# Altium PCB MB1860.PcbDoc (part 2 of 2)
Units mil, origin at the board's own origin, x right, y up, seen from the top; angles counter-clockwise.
Board outline 5005.03 x 3784.67 mil, 2 copper layers (Top Layer, Bottom Layer), stack 61.811 mil thick; 42 components, 46 nets, 183 pads, 524 vias.
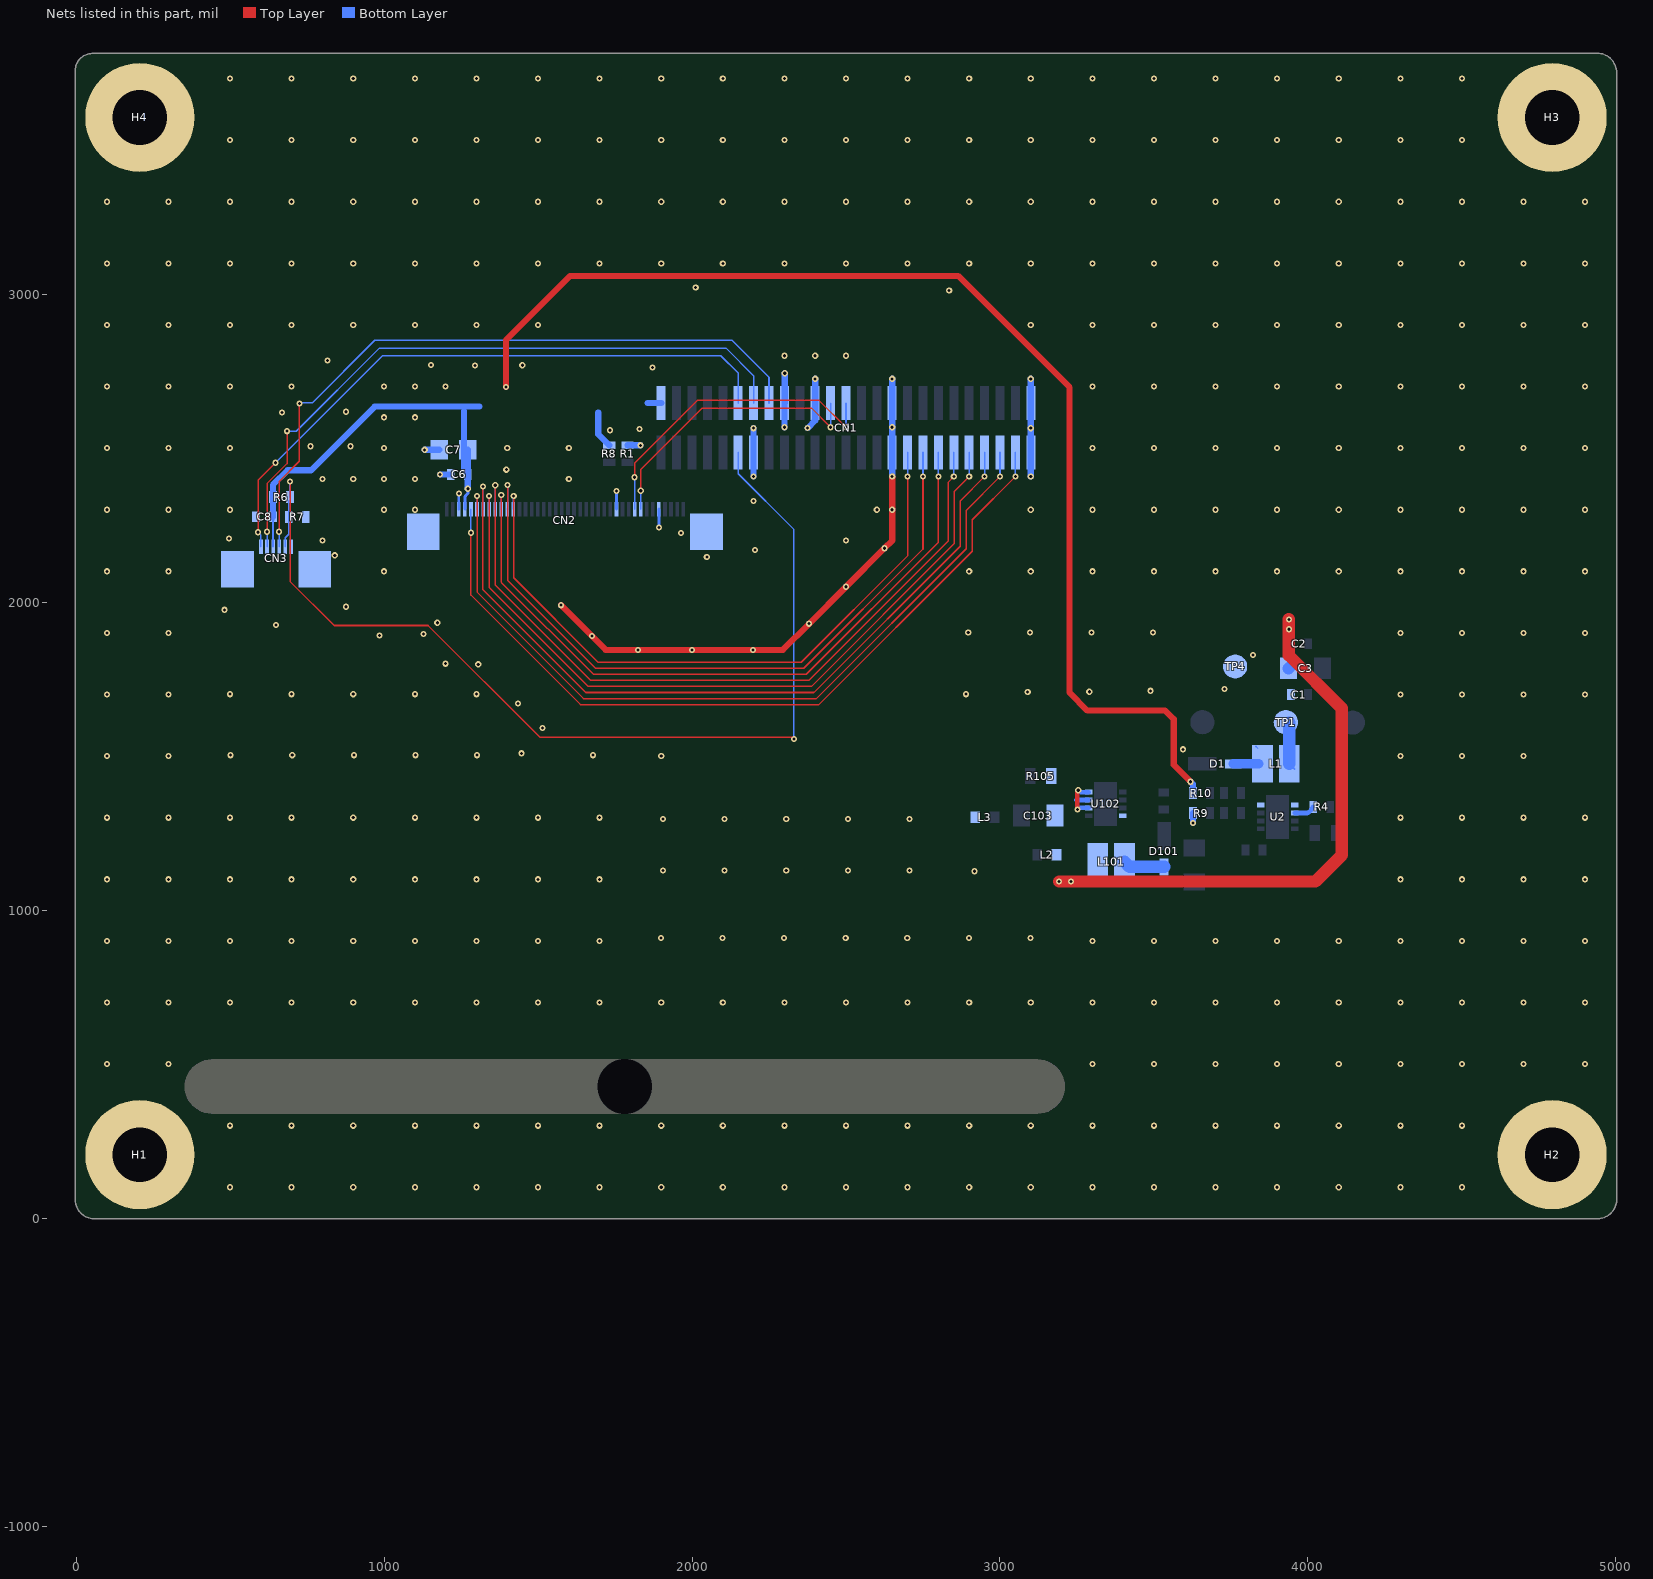
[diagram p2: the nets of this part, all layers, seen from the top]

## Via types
v1: diameter 20, hole 10, Top Layer to Bottom Layer, tented both sides, 524 vias

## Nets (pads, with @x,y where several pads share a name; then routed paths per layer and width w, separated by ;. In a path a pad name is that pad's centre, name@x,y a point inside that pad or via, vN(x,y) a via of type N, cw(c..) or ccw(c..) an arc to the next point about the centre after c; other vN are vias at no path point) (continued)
GND: C6.1 C7.2 C8.1 CN1.1 CN1.2 CN1.19 CN1.20 CN1.30 CN1.34 CN1.37 CN2.5 CN2.12 CN2.38 CN2.MP1 CN2.MP2 CN3.1 CN3.MP1 CN3.MP2 H1.1 H2.1 H3.1 H4.1 L3.1 R1.1 R7.1 R9.2 TP4.1 | length 2955.2
  Top Layer w20: v1(1575,1990) v1(1675,1890) 1720,1845 v1(1825,1845) v1(2000,1845) v1(2198,1845) 2295,1845 v1(2380,1930) v1(2500,2050) v1(2625,2175) 2650,2200 v1(2650,2300) v1(2650,2407.44)
  Bottom Layer w8: CN2.38@1242.91,2301.69 v1@1242.91,2352.46
  Bottom Layer w10: v1@1242.91,2352.46 v1(1243,2352.54) ; CN2.12@1754.73,2301.69 v1(1754.72,2360.82) ; CN2.5@1892.52,2301.69 1893,2301.21 v1(1893,2242)
  Bottom Layer w20: v1(1132,2494.54) C7.2@1179.48,2494.54 ; v1(1182,2414.54) C6.1@1216.88,2414.54 ; R1.1@1790.72,2509.1 v1(1833,2509.1) ; v1(2200,2407.44) CN1.37@2200,2486.1 v1(2200,2564.76) ; v1(2300,2567.68) CN1.34@2300,2646.34 2301,2647.34 v1(2301,2743) ; v1(2375,2565) 2400,2590 CN1.30@2400,2646.34 v1(2400,2725) ; v1(2650,2407.44) CN1.19@2650,2486.1 v1(2650,2567.68) CN1.20@2650,2646.34 v1(2650,2725) ; v1(3100,2407.44) CN1.1@3100,2486.1 v1(3100,2564.76) CN1.2@3100,2646.34 v1(3100,2725) ; v1(3626.44,1282.44) R9.2@3626.44,1315
  other v1: 500,100 700,100 900,100 1100,100 1300,100 1500,100 1700,100 1900,100 2100,100 2300,100 2500,100 2700,100 2900,100 3100,100 3300,100 3500,100 3700,100 3900,100 4100,100 4300,100 4500,100 500,300 700,300 900,300 1100,300 1300,300 1500,300 1700,300 1900,300 2100,300 2300,300 2500,300 2700,300 2900,300 3100,300 3300,300 3500,300 3700,300 3900,300 4100,300 4300,300 4500,300 100,500 300,500 3300,500 3500,500 3700,500 3900,500 4100,500 4300,500 4500,500 4700,500 4900,500 100,700 300,700 500,700 700,700 900,700 1100,700 1300,700 1500,700 1700,700 1900,700 2100,700 2300,700 2500,700 2700,700 2900,700 3100,700 3300,700 3500,700 3700,700 3900,700 4100,700 4300,700 4500,700 4700,700 4900,700 100,900 300,900 500,900 700,900 900,900 1100,900 1300,900 1500,900 1700,900 3300,900 3500,900 3700,900 3900,900 4100,900 4300,900 4500,900 4700,900 4900,900 1899,909 2099,909 2299,909 2499,909 2699,909 2899,909 3099,909 100,1100 300,1100 500,1100 700,1100 900,1100 1100,1100 1300,1100 1500,1100 1700,1100 4300,1100 4500,1100 4700,1100 4900,1100 2917,1126 1906,1128 2106,1128 2306,1128 2506,1128 2706,1128 1906,1296 2106,1296 2306,1296 2506,1296 2706,1296 100,1300 300,1300 500,1300 700,1300 900,1300 1100,1300 1300,1300 1500,1300 1700,1300 4300,1300 4500,1300 4700,1300 4900,1300 100,1500 300,1500 1900,1500 4300,1500 4500,1500 4700,1500 502,1503 702,1503 902,1503 1102,1503 1302,1503 1679,1503 1446,1509 3594,1522 1515,1591 1435,1671 100,1700 300,1700 4300,1700 4500,1700 4700,1700 4900,1700 500,1701 700,1701 900,1701 1100,1701 1300,1701 2890,1701 3090,1708 3290,1709 3489,1712 3729,1718 1306,1798 1200,1800 3822,1828 985,1892 1128,1897 100,1900 300,1900 4300,1900 4500,1900 4700,1900 4900,1900 2897,1901 3097,1901 3297,1901 3497,1901 649.61,1925.32 1173,1933 482,1975 876,1985 100,2100 300,2100 1000,2100 2900,2100 3100,2100 3300,2100 3500,2100 3700,2100 3900,2100 4100,2100 4300,2100 4500,2100 4700,2100 4900,2100 2048,2146 840,2152 2205,2169 800,2200 2500,2200 497,2207 1964.37,2224 100,2300 300,2300 500,2300 1000,2300 1100,2300 2600,2300 3100,2300 3300,2300 3500,2300 3700,2300 3900,2300 4100,2300 4300,2300 4500,2300 4700,2300 4900,2300 2200,2328 800,2400 900,2400 1000,2400 1100,2400 1600,2400 1397,2430 100,2500 300,2500 500,2500 1000,2500 1400,2500 1600,2500 3300,2500 3500,2500 3700,2500 3900,2500 4100,2500 4300,2500 4500,2500 4700,2500 4900,2500 761,2506 891,2506 1734,2558 1830,2562 1000,2600 1100,2600 669,2616 877,2618 100,2700 300,2700 500,2700 700,2700 1000,2700 1100,2700 1200,2700 3300,2700 3500,2700 3700,2700 3900,2700 4100,2700 4300,2700 4500,2700 4700,2700 4900,2700 1872,2762 1295,2768 1449,2769 1153,2770 816,2785 2300,2800 2400,2800 2500,2800 100,2900 300,2900 500,2900 700,2900 900,2900 1100,2900 1300,2900 1500,2900 3100,2900 3300,2900 3500,2900 3700,2900 3900,2900 4100,2900 4300,2900 4500,2900 4700,2900 4900,2900 2835,3012 2012,3021 100,3100 300,3100 500,3100 700,3100 900,3100 1100,3100 1300,3100 1500,3100 1700,3100 1900,3100 2100,3100 2300,3100 2500,3100 2700,3100 2900,3100 3100,3100 3300,3100 3500,3100 3700,3100 3900,3100 4100,3100 4300,3100 4500,3100 4700,3100 4900,3100 100,3300 300,3300 500,3300 700,3300 900,3300 1100,3300 1300,3300 1500,3300 1700,3300 1900,3300 2100,3300 2300,3300 2500,3300 2700,3300 2900,3300 3100,3300 3300,3300 3500,3300 3700,3300 3900,3300 4100,3300 4300,3300 4500,3300 4700,3300 4900,3300 500,3500 700,3500 900,3500 1100,3500 1300,3500 1500,3500 1700,3500 1900,3500 2100,3500 2300,3500 2500,3500 2700,3500 2900,3500 3100,3500 3300,3500 3500,3500 3700,3500 3900,3500 4100,3500 4300,3500 4500,3500 500,3700 700,3700 900,3700 1100,3700 1300,3700 1500,3700 1700,3700 1900,3700 2100,3700 2300,3700 2500,3700 2700,3700 2900,3700 3100,3700 3300,3700 3500,3700 3700,3700 3900,3700 4100,3700 4300,3700 4500,3700
HSYNC: CN1.26 CN2.9 | length 1032
  Top Layer w5: v1@1813.78,2408.78 1813.78,2451.78 2017,2655 2412.68,2655 v1(2500,2567.68)
  Bottom Layer w5: CN2.9@1813.78,2301.69 1813.78,2385.54 v1(1813.78,2405.51) ; v1(2500,2567.68) CN1.26@2500,2646.34
I2C_SCL: CN1.40 CN3.6 | length 2067.2
  Top Layer w5: v1(591,2226.86) 591,2396 v1(647.5,2452.5)
  Bottom Layer w5: v1(591,2226.86) 600.39,2217.46 CN3.6@600.39,2179.66 ; v1(647.5,2452.5) 995,2800 2093.58,2800 2150,2743.58 CN1.40@2150,2646.34
I2C_SDA: CN1.38 CN3.5 | length 2155
  Top Layer w5: v1(620.08,2228.41) 620.08,2385.08 685,2450 v1(685,2555)
  Bottom Layer w5: CN3.5@620.08,2179.66 v1(620.08,2228.41) ; v1(685,2555) 715,2555 985,2825 2110,2825 2200,2735 CN1.38@2200,2646.34
INT: CN1.39 CN3.2 R6.1 R7.2 | length 3383.7
  Top Layer w5: v1(695,2391.86) 695,2067 838,1924 1143,1924 1506,1561 2326,1561 v1(2331,1556)
  Bottom Layer w5: CN3.2@679.13,2179.66 679.13,2208.99 690.44,2220.3 R7.2@690.44,2276.86 R6.1@690.44,2329.86 ; R6.1@694.56,2340.86 694.56,2391.42 v1(695,2391.86) ; CN1.39@2150,2486.1 2150,2417 2331,2236 v1(2331,1556)
NetD1_1: D1.1 L1.2 U2.8 | length 91.5
  Bottom Layer w5: L1.2@3830.57,1532 L1.2@3836.48,1526.09
  Bottom Layer w30: D1.1@3757.39,1475 L1.2@3840.57,1475
NetD101_1: D101.1 L101.2 U102.8 | length 135.6
  Bottom Layer w40: L101.2@3404.31,1157 3421.08,1140.23 D101.1@3533,1140.23
NetR4_2: R4.2 U2.2 | length 70.3
  Bottom Layer w15: U2.2@3956.72,1315.16 3997.54,1315.16 3998.89,1316.5 4001.25,1316.5 4011.5,1326.75 4011.5,1329.11 R4.2@4017.39,1335
NetR105_2: R105.2 U102.2 U102.4 | length 138.5
  Top Layer w15: v1(3251.24,1327) 3251.24,1386 v1(3254.24,1389)
  Bottom Layer w15: v1(3251.24,1327) 3256,1331.76 U102.2@3288.12,1331.76 ; v1(3254.24,1389) 3260.29,1382.94 U102.4@3288.12,1382.94
R0: CN1.3 CN2.36 | length 2639.1
  Top Layer w5: v1(1282.28,2225.31) 1282.28,2071.77 1282.28,2022.84 1637.92,1667.2 2412.08,1667.2 2910,2165.13 2910,2267.44 v1(3050,2407.44)
  Bottom Layer w5: v1(1282.28,2225.31) CN2.36@1282.28,2301.69 ; v1(3050,2407.44) CN1.3@3050,2486.1
R1: CN1.5 CN2.35 | length 2646.8
  Top Layer w5: v1(1301.97,2344.88) 1301.97,2032.53 1647.61,1686.89 2403.92,1686.89 2890.32,2173.28 2890.32,2297.76 v1(3000,2407.44)
  Bottom Layer w5: CN2.35@1301.97,2301.69 v1(1301.97,2344.88) ; v1(3000,2407.44) CN1.5@3000,2486.1
R2: CN1.7 CN2.34 | length 2631.6
  Top Layer w5: v1(1321,2375.54) 1321,2040.5 1654.92,1706.57 2395.77,1706.57 2870.63,2181.44 2870.63,2328.07 v1(2950,2407.44)
  Bottom Layer w5: v1(1321,2375.54) 1321,2303.04 1322,2302.04 CN2.34@1321.65,2301.69 ; v1(2950,2407.44) CN1.7@2950,2486.1
R3: CN1.9 CN2.33 | length 2491.9
  Top Layer w5: v1(1341,2344.88) 1341,2048.5 1663.24,1726.26 2387.62,1726.26 2850.94,2189.59 2850.94,2358.39 v1(2900,2407.44)
  Bottom Layer w5: v1(1341,2344.88) 1341.34,2344.54 CN2.33@1341.34,2301.69 ; v1(2900,2407.44) CN1.9@2900,2486.1
R4: CN1.11 CN2.32 | length 2483.7
  Top Layer w5: v1(1361,2379.54) 1361,2055.48 1670.54,1745.94 2379.46,1745.94 2831.26,2197.74 2831.26,2388.7 v1(2850,2407.44)
  Bottom Layer w5: CN2.32@1361,2301.72 v1(1361,2379.54) ; v1(2850,2407.44) CN1.11@2850,2486.1
R5: CN1.13 CN2.31 | length 2339.2
  Top Layer w5: 1380.71,2064.19 v1(1380.71,2347.72) ; 1382.46,2062.45 1680.04,1765.63 2371.31,1765.63 2800,2194.32 v1(2800,2407.44)
  Bottom Layer w5: CN2.31@1380.71,2301.69 v1(1380.71,2347.72) ; v1(2800,2407.44) CN1.13@2800,2486.1
R6: CN1.15 CN2.30 | length 2330.1
  Top Layer w5: v1(1401,2380.54) 1401,2071.16 1686.85,1785.32 2363.15,1785.32 2750,2172.16 v1(2750,2407.44)
  Bottom Layer w5: CN2.30@1400.4,2301.69 1401,2302.3 v1(1401,2380.54) ; v1(2750,2407.44) CN1.15@2750,2486.1
R7: CN1.17 CN2.29 | length 2181
  Top Layer w5: v1(1421,2344.88) 1421,2079 1695,1805 2355,1805 2700,2150 v1(2700,2407.44)
  Bottom Layer w5: CN2.29@1420.08,2301.69 1420.08,2343.96 v1(1421,2344.88) ; v1(2700,2407.44) CN1.17@2700,2486.1
VDD: C6.2 C7.1 C8.2 CN1.50 CN2.37 CN3.4 R6.2 R8.1 R10.1 | length 5385.6
  Top Layer w20: v1(1396,2698) 1396,2851 1604,3059 2864,3059 3226,2697 3226,1706 3284,1648 3536,1648 3564,1620 3564,1472 3619,1417 v1(3618.75,1416.75)
  Bottom Layer w6: CN3.4@639.76,2179.66 C8.2@639.76,2267.53
  Bottom Layer w10: C8.2@638,2269.3 C8.2@639.76,2267.53 ; CN2.37@1262.6,2302.15 CN2.37@1262.6,2301.69 CN2.37@1262.65,2301.74 ; CN2.37@1262.91,2302.01 1263,2302.09 1263,2342.84 1264,2343.84 1264,2344.59 1272,2352.59 v1(1272,2368)
  Bottom Layer w20: C8.2@639.56,2276.86 639.44,2276.98 R6.2@639.44,2340.86 639.44,2380.44 687,2428 763,2428 970,2635 1310,2635 ; 1260,2620 1260,2429 C6.2@1272,2417 ; v1(1272,2368) C6.2@1272,2410.61 ; C6.2@1272,2414.54 C6.2@1272,2417 ; C7.1@1272,2494.54 C6.2@1272,2417 ; 1695.43,2615.43 1695.43,2545.1 R8.1@1731.43,2509.1 ; 1856.34,2646.34 CN1.50@1900,2646.34 ; v1(3618.75,1416.75) 3626.44,1409.06 R10.1@3626.44,1380
VL: C1.2 C2.2 C3.2 C103.2 L1.1 L2.2 L101.1 TP1.1 U2.1 U102.3 | length 1991.5
  Top Layer w40: v1(3192,1093) v1(3231,1093) 4024,1093 4110,1179 4110,1655 3937.39,1827.61 3938,1828.23 v1(3938,1912) v1(3938,1944)
  Bottom Layer w5: TP1.1@3937.39,1610 TP1.1@3939,1608.39 ; L1.1@3939,1475 L1.1@3956.72,1457.28
  Bottom Layer w15: 3248.59,1357.35 U102.3@3288.12,1357.35
  Bottom Layer w39.37: C3.2@3937.39,1785 C3.2@3938,1785.61
  Bottom Layer w40: L1.1@3939,1475 TP1.1@3939,1608.39
VSYNC: CN1.28 CN2.8 | length 932.4
  Top Layer w5: v1(1833.47,2361.54) 1833.47,2430.47 2033,2630 2387.68,2630 v1(2450,2567.68)
  Bottom Layer w5: CN2.8@1833.47,2301.69 v1(1833.47,2361.54) ; v1(2450,2567.68) CN1.28@2450,2646.34
WAKE: CN1.36 CN3.3 | length 2242.3
  Top Layer w5: v1(659.45,2228.41) 659.45,2391.45 725,2457 v1(725,2645) v1@725,2650
  Bottom Layer w5: CN3.3@659.45,2179.66 v1(659.45,2228.41) ; v1@722.5,2647.5 767.5,2647.5 970,2850 2130,2850 2250,2730 CN1.36@2250,2646.34
pads on no net: CN1.41 CN1.42 CN1.44 CN1.46 CN1.48 CN2.1 CN2.2 CN2.3 CN2.4 CN2.6 U2.5
copper on no net:
  other v1: 569,2410 633,2506 3154,2574 1044,2773 2998,2829 2891,2949

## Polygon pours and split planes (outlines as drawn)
GND on Bottom Layer "GND-Layer 1-No Net" (solid, remove dead copper, pour order 30): 100,40 40,100 40,3680 100,3740 4920,3740 4960,3700 4960,100 4900,40
BL_A on Bottom Layer "TOP-No Net" (solid, pour order 28): 3586,1171 3682,1171 3701,1190 3701,1254 3693,1262 3613,1262 3602,1273 3602,1328 3583,1347 3482,1347 3466,1331 3466,1204 3480,1190 3565,1190 3583,1172
BLGND on Bottom Layer "TOP-No Net" (solid, pour order 26): 4007,1950 4140,1950 4215,1875 4215,1065 4122,972 3017,972 2971,1018 2971,1496 3074.46,1599.46 3186.54,1599.46 3329,1457 3366,1457 3380,1443 3380,1437 3368.43,1425.43 3305.57,1425.43 3229,1502 3145,1502 3119.44,1476.44 3119.44,1363.83 3095.25,1339.64 3095.25,1240.25 3086,1231 3086,1104 3149,1041 3558,1041 3570,1053 3570,1096 3589,1115 3670,1115 3695,1090 3797,1090 3834,1127 3834,1209 3866,1241 3866,1373 3874,1381 3929.26,1381 3945.89,1364.37 3945.89,1170.11 3957,1159 4044,1159 4061,1176 4059,1178 4059,1368 4016,1411 4016,1636 3990,1662 3990,1933
VL on Bottom Layer "TOP-No Net" (solid, pour order 22): 3953,1969 3886,1969 3872,1955 3872,1586 3942,1516 3980,1516 3996,1532 3996,1628 3961,1663 3961,1962
VL on Bottom Layer "TOP-No Net" (solid, pour order 4): 3319.24,1065 3170.24,1065 3157.24,1078 3157.24,1356 3175.24,1374 3248.24,1374 3262.24,1360 3262.24,1346 3257.24,1341 3250.24,1341 3240.24,1331 3240.24,1271 3258.24,1253 3327.2,1253 3337.24,1242.96 3337.24,1083
NetR105_2 on Bottom Layer "TOP-No Net" (solid, pour order 10): 3288.12,1382.94 3250.29,1382.94 3239.24,1394 3198.24,1394 3188.24,1384 3155.24,1384 3148.24,1391 3148.24,1479 3155.24,1486 3223.24,1486 3295.99,1413.24 3295.99,1383
GND on Top Layer "GND-Layer 1-No Net" (solid, remove dead copper, pour order 6): 100,40 40,100 40,3680 100,3740 4920,3740 4960,3700 4960,100 4900,40
BLGND on Top Layer "TOP-No Net" (solid, pour order 2): 1896,2422 2018,2422 2180,2260 2180,2171 2170,2161 2106.64,2161 2102,2165.64 2102,2227 1981,2348 1894,2348 1884,2358 1884,2408

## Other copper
Top Layer:
  text "1" at 4363.39,990.44 h78.74
  text ".Layer_Name" at 598.19,-704.98 h118.11
  text ".GTL" at 2239.72,-704.98 h118.11
Bottom Layer:
  rectangle net BLGND: 2119,2102 2182,2228
  rectangle net BLGND: 1884,2358 1969,2543
  rectangle net VDD: 1235,2590 1915,2720
  region net BLGND: 3927.39,975 3927.39,1360 3882.39,1360 3882.39,975
  region net NetD1_1: 3853.39,1334 3853.39,1490 3808.39,1490 3808.39,1334
  region net VL: 3994,1334 3994,1536 3949.39,1536 3949.39,1334
  rectangle net NetD101_1: 3391,1131 3430,1310
  rectangle net BL_A: 3390.48,1325 3496,1338.65
  rectangle net BLGND: 3311,1331.76 3375,1444
  text "2" at 4436.57,991.71 h78.74
  text ".GBL" at 1798.65,-706.23 h118.11
  text ".Layer_Name" at 3425.18,-706.23 h118.11
Multi-Layer:
  pour cut-out: 4347.65,1053.43 4347.65,974.69 4450.01,974.69 4450.01,1053.43

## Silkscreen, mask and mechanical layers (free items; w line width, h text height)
Top Overlay:
  rectangle: 3321.87,26.83 4306.13,381.17
  lines w5: 0,57 0,3726 ; 0,61 ccw(c60.38,60.26) 61.64,-0.1 ; 0,3726.65 cw(c53.06,3726) 53.2,3779.06 ; 53.06,3779.53 4940,3779.53 ; 61.64,0 4940,0 ; 4939.46,0.35 ccw(c4939.62,60.73) 5000,60 ; 4940,3779.54 cw(c4939.27,3719.16) 4999.65,3719 ; 5000,58 5000,3719
  text "H" at 711,3481 h551.18
  text "I" at 3985,3465 h551.18
  text "E" at 3293,3452 h551.18
  text "C" at 1497,3450 h551.18
  text "J" at 2316,3394 h700
  text "MB1860B" at 503,161 h60
  text "F" at 1997,65 h551.18
  text "G" at 1312,51 h551.18
  text "S" at 2633,38 h450
  text ".Layer_Name" at 598.19,-704.98 h118.11
  text ".GTO" at 2239.72,-704.98 h118.11
Bottom Overlay:
  lines w5: 3599,1630.61 3528,1630.61 3528,1680.61 3600,1680.61 3600,1631.61 ; 3605,1867.55 3605,1818.55 3709,1818.55 ; 3606,1868.55 3709,1868.55 3709,1819.55 ; 3859,1630.61 3788,1630.61 3788,1680.61 3860,1680.61 3860,1631.61 ; 4248,1468.61 4086,1468.61 4086,1518.61 4249,1518.61 4249,1469.61
  text "GND" at 3697,1827 h30
  text "VH" at 3592,1638.61 h30
  text "VL" at 3844,1638.61 h30
  text "BLGND" at 4238,1475.61 h30
  text ".GBO" at 1798.65,-706.23 h118.11
  text ".Layer_Name" at 3425.18,-706.23 h118.11
Top Paste:
  text ".Layer_Name" at 598.19,-704.98 h118.11
  text ".GTP" at 2239.72,-704.98 h118.11
Bottom Paste:
  text ".GBP" at 1798.65,-706.23 h118.11
  text ".Layer_Name" at 3425.18,-706.23 h118.11
Top Solder:
  rectangle: 4347.65,974.69 4450.01,1053.43
  text ".Layer_Name" at 598.19,-704.98 h118.11
  text ".GTS" at 2239.72,-704.98 h118.11
Bottom Solder:
  rectangle: 4347.65,974.69 4450.01,1053.43
  text ".GBS" at 1798.65,-706.23 h118.11
  text ".Layer_Name" at 3425.18,-706.23 h118.11
M1-Board Shape:
  lines w5: 0,57 0,3726 ; 0,61 ccw(c60.38,60.26) 61.64,-0.1 ; 0,3726.65 cw(c53.06,3726) 53.2,3779.06 ; 53.06,3779.53 4940,3779.53 ; 61.64,0 4940,0 ; 4939.46,0.35 ccw(c4939.62,60.73) 5000,60 ; 4940,3779.54 cw(c4939.27,3719.16) 4999.65,3719 ; 5000,58 5000,3719
M2-Board Dimensions:
  text ".Layer_Name" at 598.19,-704.98 h118.11
  text ".GM2" at 2239.72,-704.98 h118.11
M14-Top Assembly:
  text ".Layer_Name" at 598.19,-704.98 h118.11
  text ".GM14" at 2239.72,-704.98 h118.11
M15-Bottom Assembly:
  text ".GM15" at 1798.65,-706.23 h118.11
  text ".Layer_Name" at 3425.18,-706.23 h118.11
Drill Drawing:
  drawing of 497 lines, arcs and shapes, not listed
  text "4" at 5826,5893 h75
  text "4" at 5826,5893 h75
  text "LAYER STUCK-UP" at 6026,5893 h75
  text "LAYER STUCK-UP" at 6026,5893 h75
  text "SOLDERMASK & SILKSCREEN" at 7746,5678 h60
  text "SOLDERMASK & SILKSCREEN" at 7746,5678 h60
  text "LAYER 1 (0.5 oz cu+planted)" at 7754.7,5558.7 h60
  text "LAYER 1 (0.5 oz cu+planted)" at 7754.7,5558.7 h60
  text "63 mil" at 5740.5,5400.5 h50
  text "63 mil" at 5740.5,5400.5 h50
  text "CORE" at 6766,5393 h60
  text "CORE" at 6766,5393 h60
  text "+/-10%" at 5746,5343 h40
  text "+/-10%" at 5746,5343 h40
  text "LAYER 2 (0.5 oz cu+planted)" at 7746,5198 h60
  text "LAYER 2 (0.5 oz cu+planted)" at 7746,5198 h60
  text "SOLDERMASK & SILKSCREEN" at 7746,5078 h60
  text "SOLDERMASK & SILKSCREEN" at 7746,5078 h60
  text "2 LAYER STUCKING" at 6386,4833 h75
  text "2 LAYER STUCKING" at 6386,4833 h75
  text "PCB SPECIFICATIONS :" at 5434.86,3987.21 h118.11
  text "PCB : TYPE 3" at 11241.62,3980.43 h118.11
  text "A.   MATERIAL :" at 5434.86,3829.73 h118.11
  text "FR-4" at 6950.61,3829.73 h118.11
  text "TG-170" at 7600.22,3829.73 h118.11
  text "X  TG-150" at 8318.72,3829.73 h118.11
  text "TG-140" at 8948.64,3829.73 h118.11
  text "ASPECT-RATIO, AXE Z :" at 11241.62,3763.89 h118.11
  text "B.   MATERIAL FAMILY :" at 5434.86,3711.62 h118.11
  text "N/A" at 6950.61,3711.62 h118.11
  text "C.   SOLDERMASK COLOR :" at 5434.86,3593.51 h118.11
  text "GREEN" at 6950.61,3593.51 h118.11
  text "WHITE" at 7600.22,3593.51 h118.11
  text "RED" at 8318.72,3593.51 h118.11
  text "BLACK" at 8948.64,3593.51 h118.11
  text "X  Blue ink PANTONE 2955" at 9608.03,3592 h118.11
  text "6:1 to 8:1 / LEVEL \"B\"" at 11242.36,3498.24 h118.11
  text "D.   SILKSCREEN COLOR :" at 5434.86,3475.4 h118.11
  text "X  WHITE" at 6950.61,3475.4 h118.11
  text "YELLOW" at 7600.22,3475.4 h118.11
  text "BLACK" at 8318.72,3475.4 h118.11
  text "Blue ink PANTONE 2955" at 8948.64,3475.4 h118.11
  text "E.   SURFACE FINISH :" at 5434.86,3357.29 h118.11
  text "X  ENIG" at 6950.61,3357.29 h118.11
  text "IMMERSION SILVER" at 7600.22,3357.29 h118.11
  text "IMMERSION TIN" at 8948.64,3357.29 h118.11
  text "MINIMUM PARAMETERS" at 11243.42,3277.73 h118.11
  text "HASL" at 6950.61,3239.18 h118.11
  text "HASL (PB-FREE)" at 7600.22,3239.18 h118.11
  text "GOLDEN FINGER" at 8948.64,3239.18 h118.11
  text "F.   IMPEDANCE CONTROL :" at 5434.86,3121.07 h118.11
  text "X   NO" at 6950.61,3121.07 h118.11
  text "YES  (SEE IMPEDANCE TABLE FOR DETAIL INFORMATION)" at 7600.22,3121.07 h118.11
  text "DEFAULT" at 11243.42,3061.19 h118.11
  text "G.   THROUGH VIA :" at 5434.86,3002.96 h118.11
  text "PLUG THE VIAS WHICH ARE COVERED WITH SOLDERMASK ONE OR TWO SIDE." at 6950.61,3002.96 h118.11
  text "PLUG MATERIAL :" at 6950.61,2884.85 h118.11
  text "X  SOLDERMASK" at 7954.55,2884.85 h118.11
  text "NON-CONDUCTIVE EPOXY." at 8948.64,2884.85 h118.11
  text "TRACKS : 0.127mm           / GAPS : 0.1274mm" at 11243.42,2834.82 h118.11
  text "H.   STACK-UP :" at 5434.86,2766.74 h118.11
  text "SEE LAYER STACK-UP SEQUENCE FOR OVERALL THICKNESS." at 6950.61,2766.74 h118.11
  text "Symbol" at 5519.5,2085.94 h72
  text "Count" at 6025.38,2085.94 h72
  text "Hole Size" at 6625.22,2085.94 h72
  text "Plated" at 7764.88,2085.94 h72
  text "Hole Type" at 8270.76,2085.94 h72
  text "Drill Layer Pair" at 9004.56,2085.94 h72
  text "Via/Pad" at 10504.11,2085.94 h72
  text "Pad Shape" at 11093.96,2085.94 h72
  text "Template" at 11839.76,2085.94 h72
  text "Description" at 13299.32,2085.94 h72
  text "Hole Tolerance (+)" at 14153.09,2085.94 h72
  text "Hole Tolerance (-)" at 15486.69,2085.94 h72
  text "1" at 6025.38,1935.94 h60
  text "177.17mil (4.500mm)" at 6625.22,1935.94 h60
  text "NPTH" at 7764.88,1935.94 h60
  text "Slot" at 8270.76,1935.94 h60
  text "Top Layer - Bottom Layer" at 9004.56,1935.94 h60
  text "Pad" at 10504.11,1935.94 h60
  text "Rounded" at 11093.96,1935.94 h60
  text "r7264_450hn450_7264r100" at 11839.76,1935.94 h60
  text "4" at 6025.38,1785.94 h60
  text "177.17mil (4.500mm)" at 6625.22,1785.94 h60
  text "PTH" at 7764.88,1785.94 h60
  text "Round" at 8270.76,1785.94 h60
  text "Top Layer - Bottom Layer" at 9004.56,1785.94 h60
  text "Pad" at 10504.11,1785.94 h60
  text "Rounded" at 11093.96,1785.94 h60
  text "c900h450m905" at 11839.76,1785.94 h60
  text "524" at 6025.38,1635.94 h60
  text "10.00mil (0.254mm)" at 6625.22,1635.94 h60
  text "PTH" at 7764.88,1635.94 h60
  text "Round" at 8270.76,1635.94 h60
  text "Top Layer - Bottom Layer" at 9004.56,1635.94 h60
  text "Via" at 10504.11,1635.94 h60
  text "Rounded" at 11093.96,1635.94 h60
  text "v51h25m0mx0(Tol8-8)" at 11839.76,1635.94 h60
  text "3.00mil (0.076mm)" at 14153.09,1635.94 h60
  text "3.00mil (0.076mm)" at 15486.69,1635.94 h60
  text "529 Total" at 6025.38,1485.94 h60
  text "Slot definitions :" at 5519.5,1340.97 h60
  text "Routed Path Length" at 6552.19,1340.97 h60
  text "= Calculated from tool start centre position to tool end centre position." at 7654.86,1340.97 h60
  text "Hole Length" at 6552.19,1240.99 h60
  text "= Routed Path Length + Tool Size = Slot length as defined in the PCB layout" at 7244.99,1240.99 h60
  text ".Layer_Name" at 598.19,-704.98 h118.11
  text ".DRL" at 2239.72,-704.98 h118.11
M20-Top Title Box:
  circle w10: c3669.22,-969.57 r51.18
  region: 3650.53,-684.67 3039.22,-684.67 3011.89,-754.57 2964.22,-802.79 2909.22,-729.57 2909.22,-664.57 2954.22,-609.57 3010.76,-594.67 3650.53,-594.67
  region: 3099.22,-1012.61 2675.76,-1012.61 2714.87,-914.46 3024.22,-914.46 3041.89,-884.57 3128.84,-984.9
  lines w10: 2714.87,-914.46 3061,-914.46 2940.29,-775.18 cw(c3011.3,-698.65) 3020.76,-594.67 3680.76,-594.67 3650.76,-684.67 ; 2845.33,-584.94 cw(c2940.84,-623.15) 2950.16,-520.7 ; 2846.87,-583.66 2675.76,-1012.61 3436.49,-1012.61 ccw(c3446.28,-904.95) 3546.64,-945.1 ; 2915.36,-738.58 3128.84,-984.9 ; 2925.36,-738.58 3134.22,-979.57 ; 2925.36,-728.58 3134.22,-969.57 ; 2929.22,-684.67 3440.76,-684.67 ; 2930.36,-723.58 3139.22,-964.57 ; 2935.36,-718.58 3144.22,-959.57 ; 2940.36,-713.58 3149.22,-954.57 ; 2945.36,-708.58 3154.22,-949.57 ; 2947.52,-631.71 3156.38,-872.7 ; 2950.21,-520.7 3715.94,-520.7 3546.68,-945 ; 2950.36,-703.58 3157.08,-942.09 ; 2950.36,-693.58 3159.22,-934.57 ; 2950.36,-683.58 3159.22,-924.57 ; 2950.36,-648.58 3159.22,-889.57 ; 2955.36,-678.58 3164.22,-919.57 ; 2955.36,-663.58 3164.22,-904.57 ; 3009.37,-914.99 ccw(c3013.5,-893.92) 3025.22,-875.92 ; 3052.14,-684.15 ccw(c3051.12,-706.48) 3038.12,-724.67 3131.22,-832.1 cw(c3060.21,-908.63) 3089.05,-1008.97 ; 3299.44,-1004.57 3413.19,-674.67 ; 3308.19,-1002.61 3421.16,-675.02 ; 3313.19,-1002.61 3426.16,-675.02 ; 3323.19,-1002.61 3436.16,-675.02 ; 3333.19,-1002.61 3446.16,-675.02 ; 3343.19,-1002.61 3456.16,-675.02 ; 3353.19,-1002.61 3466.16,-675.02 ; 3363.19,-1002.61 3476.16,-675.02 ; 3373.19,-1002.61 3486.16,-675.02 ; 3383.19,-1002.61 3496.16,-675.02 ; 3391.41,-1004.57 3505.16,-674.67 ; 3505.16,-684.67 3650.53,-684.67 ; 3624.22,-684.57 3654.22,-594.57 ; 3630.76,-684.67 3660.76,-594.67 ; 3640.76,-684.67 3670.76,-594.67
  lines w11.81: 243.85,-968.75 2606.06,-968.75 ; 243.85,-771.9 2606.06,-771.9 ; 243.85,-575.05 2606.06,-575.05 ; 1818.66,-1165.6 1818.66,-575.05 ; 2606.06,-1165.6 2606.06,-378.2 ; 3299.44,-1004.57 3391.41,-1004.57 ; 243.87,-1165.6 243.87,-378.2 3787.16,-378.2 3787.16,-1165.6 243.85,-1165.6
  text "Project: '.Board_Name'" at 283.23,-504.82 h118.11
  text "Layer:" at 283.24,-704.98 h118.11
  text "Gerber:" at 1857.59,-704.98 h118.11
  text "Variant: '.VariantName'" at 283.23,-901.83 h118.11
  text "Ref: '.Board_Reference'" at 1862.59,-901.83 h118.11
  text "R" at 3649.22,-999.57 h60
  text "Date: '.Board_Document_Date'" at 283.23,-1098.68 h118.11
  text "Rev: '.Board_PCB_Revision'" at 1860.35,-1098.68 h118.11
M21-Bottom Title Box:
  circle w10: c369.16,-969.57 r51.18
  region: 939.16,-1012.61 1362.63,-1012.61 1323.52,-914.46 1014.16,-914.46 996.5,-884.57 909.54,-984.9
  region: 387.85,-684.67 999.16,-684.67 1026.5,-754.57 1074.16,-802.79 1129.16,-729.57 1129.16,-664.57 1084.16,-609.57 1027.63,-594.67 387.85,-594.67
  lines w10: 367.63,-594.67 397.63,-684.67 ; 377.63,-594.67 407.63,-684.67 ; 384.16,-594.57 414.16,-684.57 ; 387.63,-684.67 357.63,-594.67 1017.63,-594.67 cw(c1027.08,-698.65) 1098.1,-775.18 977.38,-914.46 1323.52,-914.46 ; 387.85,-684.67 533.22,-684.67 ; 491.7,-945 322.44,-520.7 1088.18,-520.7 ; 491.74,-945.1 ccw(c592.11,-904.95) 601.9,-1012.61 1362.63,-1012.61 1191.52,-583.66 ; 533.22,-674.67 646.98,-1004.57 ; 542.23,-675.02 655.19,-1002.61 ; 552.23,-675.02 665.19,-1002.61 ; 562.23,-675.02 675.19,-1002.61 ; 572.23,-675.02 685.19,-1002.61 ; 582.23,-675.02 695.19,-1002.61 ; 592.23,-675.02 705.19,-1002.61 ; 597.63,-684.67 1109.16,-684.67 ; 602.23,-675.02 715.19,-1002.61 ; 612.23,-675.02 725.19,-1002.61 ; 617.23,-675.02 730.19,-1002.61 ; 625.19,-674.67 738.95,-1004.57 ; 874.16,-919.57 1083.02,-678.58 ; 874.16,-904.57 1083.02,-663.58 ; 879.16,-934.57 1088.02,-693.58 ; 879.16,-924.57 1088.02,-683.58 ; 879.16,-889.57 1088.02,-648.58 ; 881.31,-942.09 1088.02,-703.58 ; 882.01,-872.7 1090.87,-631.71 ; 884.16,-949.57 1093.02,-708.58 ; 889.16,-954.57 1098.02,-713.58 ; 894.16,-959.57 1103.02,-718.58 ; 899.16,-964.57 1108.02,-723.58 ; 904.16,-979.57 1113.02,-738.58 ; 904.16,-969.57 1113.02,-728.58 ; 909.54,-984.9 1123.02,-738.58 ; 949.33,-1008.97 cw(c978.18,-908.63) 907.16,-832.1 1000.26,-724.67 ccw(c987.26,-706.48) 986.24,-684.15 ; 1013.16,-875.92 ccw(c1024.88,-893.92) 1029.02,-914.99 ; 1088.23,-520.7 cw(c1097.54,-623.15) 1193.06,-584.94
  lines w11.81: 646.98,-1004.57 738.95,-1004.57 ; 1424.96,-1165.61 1424.96,-378.2 ; 1424.96,-968.75 3787.16,-968.75 ; 1424.96,-771.9 3787.16,-771.9 ; 1424.96,-575.05 3787.16,-575.05 ; 2212.36,-1165.61 2212.36,-575.05 ; 243.85,-1165.6 3787.16,-1165.6 3787.16,-378.2 243.85,-378.2 243.85,-1165.61
  text "Project: '.Board_Name'" at 3740.15,-504.82 h118.11
  text "Gerber:" at 2165.79,-704.98 h118.11
  text "Layer:" at 3740.14,-704.98 h118.11
  text "Ref: '.Board_Reference'" at 2165.79,-901.83 h118.11
  text "Variant: '.VariantName'" at 3740.15,-901.83 h118.11
  text "R" at 389.16,-999.57 h60
  text "Rev: '.Board_PCB_Revision'" at 2168.04,-1098.68 h118.11
  text "Date: '.Board_Document_Date'" at 3740.15,-1098.68 h118.11

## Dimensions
4792.91,3573.62 to 207.09,3573.62 on Drill Drawing
207.09,3573.62 to 207.09,205.91 on Drill Drawing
